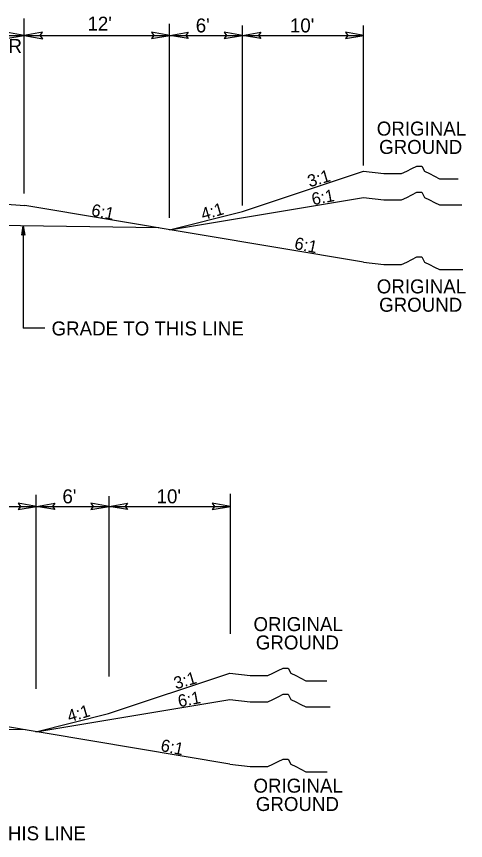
# Model space of a CAD drawing. Extents: x 2176156 to 2177167, y 76401 to 76644.
# Drawn here: x 2176331 to 2176368.1, y 76466.3 to 76534.2 of the extents above; entities that cross this region are included whole.
import ezdxf

# ---------------------------------------------------------------- set-up
doc = ezdxf.new("R2010")
doc.units = 0
for name, color, linetype in [('Exist Building', 7, 'Continuous'), ('Exist Roads Curbs', 7, 'Continuous'), ('Exist Roads EOP Other', 7, 'Continuous'), ('Exist Roads Soil', 7, 'Continuous'), ('Exist Structure Minor Culvert Topo', 7, 'Continuous'), ('Old_Level_1', 7, 'Continuous'), ('Old_Level_3', 7, 'Continuous')]:
    doc.layers.add(name, color=color, linetype=linetype)

msp = doc.modelspace()

# ---------------------------------------------------------------- linework, layer by layer
at = {"layer": 'Exist Building'}
for p, q in [((2176342.792, 76516.795), (2176302.609, 76517.393)), ((2176331.782, 76475.406), (2176308.709, 76475.749))]:
    msp.add_line(p, q, dxfattribs=at)
at = {"layer": 'Exist Roads Curbs'}
for points in [[(2176359.676, 76521.481), (2176361.347, 76521.273), (2176361.764, 76521.273), (2176362.392, 76521.273), (2176362.809, 76521.273), (2176363.227, 76521.481), (2176363.645, 76521.691), (2176364.062, 76521.901), (2176364.48, 76521.901), (2176364.69, 76521.481), (2176365.107, 76521.273), (2176365.525, 76521.064), (2176365.943, 76520.856), (2176366.36, 76520.856), (2176366.778, 76520.856), (2176367.196, 76520.856), (2176367.467, 76520.856)], [(2176359.676, 76519.315), (2176361.347, 76519.107), (2176361.765, 76519.107), (2176362.392, 76519.107), (2176362.81, 76519.107), (2176363.227, 76519.315), (2176363.645, 76519.524), (2176364.063, 76519.734), (2176364.48, 76519.734), (2176364.69, 76519.315), (2176365.108, 76519.107), (2176365.525, 76518.897), (2176365.943, 76518.689), (2176366.361, 76518.689), (2176366.778, 76518.689), (2176367.196, 76518.689), (2176367.614, 76518.689), (2176367.777, 76518.689)], [(2176359.676, 76513.981), (2176361.347, 76513.773), (2176361.764, 76513.773), (2176362.392, 76513.773), (2176362.809, 76513.773), (2176363.227, 76513.981), (2176363.645, 76514.191), (2176364.062, 76514.401), (2176364.48, 76514.401), (2176364.69, 76513.981), (2176365.107, 76513.773), (2176365.525, 76513.564), (2176365.943, 76513.356), (2176366.36, 76513.356), (2176366.778, 76513.356), (2176367.196, 76513.356), (2176367.613, 76513.356), (2176367.854, 76513.356)], [(2176348.647, 76480.095), (2176350.318, 76479.887), (2176350.735, 76479.887), (2176351.363, 76479.887), (2176351.78, 76479.887), (2176352.198, 76480.095), (2176352.616, 76480.305), (2176353.033, 76480.515), (2176353.451, 76480.515), (2176353.661, 76480.095), (2176354.078, 76479.887), (2176354.496, 76479.678), (2176354.914, 76479.47), (2176355.331, 76479.47), (2176355.749, 76479.47), (2176356.167, 76479.47), (2176356.584, 76479.47), (2176356.653, 76479.47)], [(2176348.647, 76477.929), (2176350.318, 76477.721), (2176350.736, 76477.721), (2176351.363, 76477.721), (2176351.781, 76477.721), (2176352.198, 76477.929), (2176352.616, 76478.138), (2176353.033, 76478.348), (2176353.451, 76478.348), (2176353.661, 76477.929), (2176354.078, 76477.721), (2176354.496, 76477.511), (2176354.914, 76477.303), (2176355.331, 76477.303), (2176355.749, 76477.303), (2176356.167, 76477.303), (2176356.584, 76477.303), (2176356.906, 76477.303)], [(2176348.647, 76472.595), (2176350.318, 76472.387), (2176350.735, 76472.387), (2176351.363, 76472.387), (2176351.78, 76472.387), (2176352.198, 76472.595), (2176352.616, 76472.805), (2176353.033, 76473.015), (2176353.451, 76473.015), (2176353.661, 76472.595), (2176354.078, 76472.387), (2176354.496, 76472.178), (2176354.914, 76471.97), (2176355.331, 76471.97), (2176355.749, 76471.97), (2176356.167, 76471.97), (2176356.584, 76471.97), (2176356.678, 76471.97)]]:
    msp.add_lwpolyline(points, dxfattribs=at)
at = {"layer": 'Exist Roads EOP Other'}
for p, q in [((2176349.676, 76518.148), (2176359.676, 76521.481)), ((2176325.689, 76519.123), (2176331.724, 76518.64)), ((2176343.676, 76516.648), (2176349.676, 76518.148)), ((2176338.647, 76476.762), (2176348.647, 76480.095)), ((2176332.647, 76475.262), (2176338.647, 76476.762))]:
    msp.add_line(p, q, dxfattribs=at)
at = {"layer": 'Exist Roads Soil'}
for p, q in [((2176343.676, 76516.648), (2176359.676, 76519.315)), ((2176359.676, 76513.981), (2176331.724, 76518.64)), ((2176332.647, 76475.262), (2176348.647, 76477.929)), ((2176348.647, 76472.595), (2176320.695, 76477.254))]:
    msp.add_line(p, q, dxfattribs=at)
at = {"layer": 'Old_Level_1'}
for points in [[(2176330.179, 76532.402), (2176331.689, 76532.662), (2176330.171, 76532.93), (2176330.364, 76532.662)], [(2176333.199, 76532.922), (2176331.689, 76532.662), (2176333.207, 76532.393), (2176333.014, 76532.662)], [(2176342.179, 76532.402), (2176343.689, 76532.662), (2176342.171, 76532.93), (2176342.364, 76532.662)], [(2176345.199, 76532.402), (2176343.689, 76532.662), (2176345.207, 76532.93), (2176345.014, 76532.662)], [(2176348.179, 76532.402), (2176349.689, 76532.662), (2176348.171, 76532.93), (2176348.364, 76532.662)], [(2176351.199, 76532.402), (2176349.689, 76532.662), (2176351.207, 76532.93), (2176351.014, 76532.662)], [(2176358.179, 76532.402), (2176359.689, 76532.662), (2176358.171, 76532.93), (2176358.364, 76532.662)], [(2176331.479, 76516.207), (2176331.609, 76516.962), (2176331.743, 76516.203), (2176331.609, 76516.299)], [(2176331.185, 76493.58), (2176332.695, 76493.84), (2176331.177, 76494.108), (2176331.37, 76493.84)], [(2176334.205, 76493.58), (2176332.695, 76493.84), (2176334.213, 76494.108), (2176334.02, 76493.84)], [(2176337.185, 76493.58), (2176338.695, 76493.84), (2176337.177, 76494.108), (2176337.37, 76493.84)], [(2176340.205, 76493.58), (2176338.695, 76493.84), (2176340.213, 76494.108), (2176340.02, 76493.84)], [(2176347.185, 76493.58), (2176348.695, 76493.84), (2176347.177, 76494.108), (2176347.37, 76493.84)]]:
    msp.add_lwpolyline(points, close=True, dxfattribs=at)
at = {"layer": 'Old_Level_3'}
for p, q in [((2176331.689, 76519.627), (2176331.689, 76534.057)), ((2176343.676, 76517.634), (2176343.676, 76533.627)), ((2176349.676, 76518.652), (2176349.676, 76533.494)), ((2176359.676, 76521.954), (2176359.676, 76533.494)), ((2176295.689, 76532.662), (2176359.676, 76532.662)), ((2176331.609, 76516.962), (2176331.609, 76508.536)), ((2176333.376, 76508.536), (2176331.609, 76508.536)), ((2176332.682, 76478.812), (2176332.682, 76494.805)), ((2176348.696, 76483.329), (2176348.696, 76494.869)), ((2176338.682, 76479.83), (2176338.682, 76494.672)), ((2176320.695, 76493.84), (2176332.695, 76493.84)), ((2176332.695, 76493.84), (2176338.695, 76493.84)), ((2176338.695, 76493.84), (2176348.695, 76493.84))]:
    msp.add_line(p, q, dxfattribs=at)

# ---------------------------------------------------------------- texts
at = {"layer": 'Exist Roads Curbs'}
for s, rotation, p in [('3:1', 16.46494, (2176355.223, 76520.136)), ('6:1', 10.81682, (2176355.49, 76518.667)), ('6:1', 348.51345, (2176337.158, 76517.816)), ('4:1', 16.46494, (2176346.433, 76517.416)), ('6:1', 348.51345, (2176353.908, 76515.075)), ('3:1', 16.46494, (2176344.194, 76478.75)), ('6:1', 10.81682, (2176344.461, 76477.281)), ('4:1', 16.46494, (2176335.404, 76476.03)), ('6:1', 348.51345, (2176342.879, 76473.689))]:
    msp.add_text(s, height=1.0064, rotation=rotation, dxfattribs=at).set_placement(p)
at = {"layer": 'Exist Structure Minor Culvert Topo'}
for s, height, p in [("12' ", 1.1533, (2176336.903, 76533.057)), ("6'", 1.1533, (2176345.831, 76532.914)), ("10'", 1.1533, (2176353.597, 76532.914)), ('SHOULDER', 1.1533, (2176322.934, 76531.22)), ('ORIGINAL', 1.1533, (2176360.759, 76524.408)), ('GROUND', 1.1533, (2176360.953, 76522.896)), ('ORIGINAL', 1.1533, (2176360.759, 76511.399)), ('GROUND', 1.1533, (2176360.953, 76509.887)), ('GRADE TO THIS LINE', 1.15334, (2176333.939, 76507.932)), ("6'", 1.1533, (2176334.837, 76494.092)), ("10'", 1.1533, (2176342.603, 76494.092)), ('ORIGINAL', 1.1533, (2176350.592, 76483.558)), ('GROUND', 1.1533, (2176350.786, 76482.046)), ('ORIGINAL', 1.1533, (2176350.592, 76470.24)), ('GROUND', 1.1533, (2176350.786, 76468.728)), ('GRADE TO THIS LINE', 1.15334, (2176320.915, 76466.311))]:
    msp.add_text(s, height=height, dxfattribs=at).set_placement(p)

doc.saveas('drawing.dxf')
